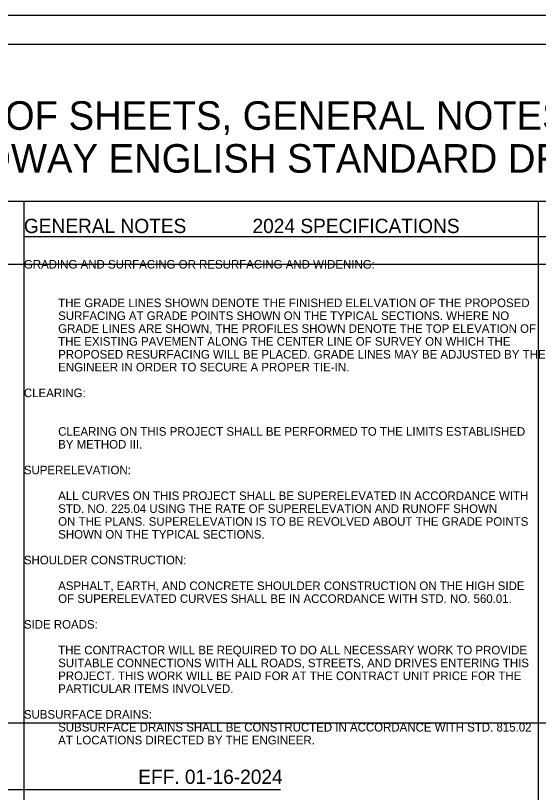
# Model space of a CAD drawing. Extents: x 573076.3 to 573113.7, y -55253.8 to -55199.3.
# Drawn here: x 573091.37 to 573100.52, y -55212.89 to -55199.3 of the extents above; entities that cross this region are included whole.
import ezdxf

# ---------------------------------------------------------------- set-up
doc = ezdxf.new("R2010")
doc.units = 0
for name, color, linetype in [('Prop DSN Text', 7, 'Continuous'), ('Scratch_Level_1', 7, 'Continuous'), ('Sheet Data Field CELL', 7, 'Continuous'), ('Sheet Plan CELL', 7, 'Continuous'), ('Sheet Plot Border Inside CELL', 7, 'Continuous')]:
    doc.layers.add(name, color=color, linetype=linetype)

msp = doc.modelspace()

# ---------------------------------------------------------------- linework, layer by layer
at = {"layer": 'Prop DSN Text'}
for p, q in [((573091.514, -55203.165), (573104.001, -55203.165)), ((573082.514, -55212.842), (573096.001, -55212.842))]:
    msp.add_line(p, q, dxfattribs=at)
at = {"layer": 'Scratch_Level_1'}
for p, q in [((573111.514, -55202.55), (573076.255, -55202.55)), ((573091.514, -55202.55), (573091.514, -55220.798)), ((573100.514, -55202.55), (573100.514, -55220.798)), ((573082.514, -55203.65), (573112.708, -55203.65)), ((573082.514, -55211.674), (573113.454, -55211.674))]:
    msp.add_line(p, q, dxfattribs=at)
at = {"layer": 'Sheet Plan CELL'}
msp.add_lwpolyline([(573081.514, -55199.798), (573111.514, -55199.798), (573111.514, -55220.798), (573081.514, -55220.798)], close=True, dxfattribs=at)
at = {"layer": 'Sheet Plot Border Inside CELL'}
msp.add_lwpolyline([(573112.014, -55199.298), (573078.014, -55199.298), (573078.014, -55221.298), (573112.014, -55221.298)], close=True, dxfattribs=at)

# ---------------------------------------------------------------- texts
at = {"layer": 'Prop DSN Text'}
for s, height, p in [('GENERAL NOTES', 0.25, (573091.514, -55203.104)), ('2024 SPECIFICATIONS', 0.25, (573095.514, -55203.104)), ('GRADING AND SURFACING OR RESURFACING AND WIDENING:', 0.15, (573091.514, -55203.725)), ('THE GRADE LINES SHOWN DENOTE THE FINISHED ELELVATION OF THE PROPOSED', 0.15, (573092.114, -55204.4)), ('SURFACING AT GRADE POINTS SHOWN ON THE TYPICAL SECTIONS. WHERE NO', 0.15, (573092.114, -55204.625)), ('GRADE LINES ARE SHOWN, THE PROFILES SHOWN DENOTE THE TOP ELEVATION OF', 0.15, (573092.114, -55204.85)), ('THE EXISTING PAVEMENT ALONG THE CENTER LINE OF SURVEY ON WHICH THE ', 0.15, (573092.114, -55205.075)), ('PROPOSED RESURFACING WILL BE PLACED. GRADE LINES MAY BE ADJUSTED BY THE', 0.15, (573092.114, -55205.3)), ('ENGINEER IN ORDER TO SECURE A PROPER TIE-IN.', 0.15, (573092.114, -55205.525)), ('CLEARING:', 0.15, (573091.514, -55205.975)), ('CLEARING ON THIS PROJECT SHALL BE PERFORMED TO THE LIMITS ESTABLISHED', 0.15, (573092.114, -55206.65)), ('BY METHOD III.', 0.15, (573092.114, -55206.875)), ('SUPERELEVATION:', 0.15, (573091.514, -55207.325)), ('ALL CURVES ON THIS PROJECT SHALL BE SUPERELEVATED IN ACCORDANCE WITH', 0.15, (573092.114, -55207.775)), ('STD. NO. 225.04 USING THE RATE OF SUPERELEVATION AND RUNOFF SHOWN', 0.15, (573092.114, -55208)), ('ON THE PLANS. SUPERELEVATION IS TO BE REVOLVED ABOUT THE GRADE POINTS', 0.15, (573092.114, -55208.225)), ('SHOWN ON THE TYPICAL SECTIONS.', 0.15, (573092.114, -55208.45)), ('SHOULDER CONSTRUCTION:', 0.15, (573091.514, -55208.9)), ('ASPHALT, EARTH, AND CONCRETE SHOULDER CONSTRUCTION ON THE HIGH SIDE', 0.15, (573092.114, -55209.35)), ('OF SUPERELEVATED CURVES SHALL BE IN ACCORDANCE WITH STD. NO. 560.01.', 0.15, (573092.114, -55209.575)), ('SIDE ROADS:', 0.15, (573091.514, -55210.025)), ('THE CONTRACTOR WILL BE REQUIRED TO DO ALL NECESSARY WORK TO PROVIDE', 0.15, (573092.114, -55210.475)), ('SUITABLE CONNECTIONS WITH ALL ROADS, STREETS, AND DRIVES ENTERING THIS', 0.15, (573092.114, -55210.7)), ('PROJECT. THIS WORK WILL BE PAID FOR AT THE CONTRACT UNIT PRICE FOR THE', 0.15, (573092.114, -55210.925)), ('PARTICULAR ITEMS INVOLVED.', 0.15, (573092.114, -55211.15)), ('SUBSURFACE DRAINS:', 0.15, (573091.514, -55211.6)), ('SUBSURFACE DRAINS SHALL BE CONSTRUCTED IN ACCORDANCE WITH STD. 815.02', 0.15, (573092.114, -55211.825)), ('AT LOCATIONS DIRECTED BY THE ENGINEER.', 0.15, (573092.114, -55212.05)), ('EFF. 01-16-2024', 0.25, (573093.514, -55212.742))]:
    msp.add_text(s, height=height, dxfattribs=at).set_placement(p)
at = {"layer": 'Sheet Data Field CELL'}
for s, p in [('INDEX OF SHEETS, GENERAL NOTES AND', (573088.952, -55201.298)), ('2024 ROADWAY ENGLISH STANDARD DRAWINGS', (573087.683, -55202.048))]:
    msp.add_text(s, height=0.5, dxfattribs=at).set_placement(p)

doc.saveas('drawing.dxf')
